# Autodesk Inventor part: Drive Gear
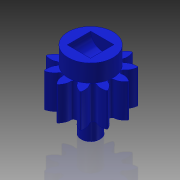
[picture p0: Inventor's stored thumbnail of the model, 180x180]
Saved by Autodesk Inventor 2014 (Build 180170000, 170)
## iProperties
Created: 2015-06
Part Number: Drive Gear
Material: Generic
Document SubType Name: Modeling
Designer: Brad Factor
Density: 1 g/cm^3
Appearance: Blue - Wall Paint - Glossy
Sending System: SolidWorks 2013
Last Author: Akzl
Author: Brad Factor
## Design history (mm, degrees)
node "Drive_Wheel"
sketch "Sketch1"
  geometry: C1 r 1.195 at (0, 0) reference; C2 r 1.194 at (0, 0); C3 r 2.4 at (0, 0) reference; C4 r 1.195 at (0, 0)
  constraints: 2 centre point, 1 coincident, 1 concentric
  dimensions: "d34" = 2.3876 diameter of C2
extrude "Shaft ID Adjustment" join sketch "Sketch1" stored distance "d1" = 10; taper "d2" = 0 deg
sketch "Sketch2"
  geometry: C1 r 2.4 at (0, 0) reference; C2 r 2.781 at (0, 0)
  constraints: 1 centre point
  dimensions: "d3" = 0.381 radial gap between concentric circles of C1 C2
extrude "Shaft OD Adjustment" join sketch "Sketch2" stored distance "d4" = 10; taper "d5" = 0 deg
sketch "Sketch3"
  geometry: C1 r 4.85 at (0, 0) reference; C2 r 5.612 at (0, 0)
  constraints: 1 centre point
  dimensions: "d6" = 0.762 radial gap between concentric circles of C1 C2
extrude "Magnet Holder OD Adjustment" join sketch "Sketch3" stored distance "d7" = 10; taper "d8" = 0 deg
sketch "Sketch4"
  geometry: C1 r 5.612 at (0, 0) reference; C2 r 2.781 at (0, 0) reference; C3 r 5.612 at (0, 0); C4 r 2.781 at (0, 0)
  constraints: 2 centre point, 2 coincident, 2 concentric
extrude "Magnet Holder Depth Adjustment" join sketch "Sketch4" distance "d17" = 0.79375; taper "d18" = 0 deg
chamfer "Outer Shaft Chamfer" distance "d9" = 0.254; stored, may be unused: second distance "d10" = 1.25, angle "d11" = 45 deg
chamfer "Inner Shaft Chamfer" distance "d12" = 0.254; stored, may be unused: second distance "d13" = 1.25, angle "d14" = 45 deg
feature "Magnet Recess Adjustment" dims "d15" = 0.127, "d16" = 0.127
workplane "Work Plane1"
workplane "Work Plane2"
sketch "Sketch5"
  geometry: C1 r 2.781 at (0, 0) reference; C2 r 5.612 at (0, 0) reference; C3 r 2.781 at (0, 0); C4 r 5.612 at (0, 0)
  constraints: 2 centre point, 2 coincident, 2 concentric
extrude "Gear Root Depth" join sketch "Sketch5" stored distance "d20" = 10; taper "d21" = 0 deg
sketch "Sketch6"
  geometry: C1 r 5.612 at (0, 0) reference; C2 r 9.792 at (0, 0); C3 r 5.612 at (0, 0)
  constraints: 2 centre point, 2 coincident, 1 concentric
  dimensions: "d22" = 19.5834 diameter of C2
extrude "Gear OD Extrusion" join sketch "Sketch6" stored distance "d23" = 10; taper "d24" = 0 deg
sketch "Sketch8"
  geometry: C1 r 7.761 at (0, 0) reference; C2 r 7.293 at (0, 0) reference; C3 r 6.622 at (0, 0) reference; A1 r 9.796 centre (0, 0) between (-2.559, 9.456) and (2.559, 9.456) reference; 54 further points
  constraints: 4 centre point, 2 point on circle, 115 other
extrude "Gear Tooth" cut sketch "Sketch8" stored distance "d25" = 10; taper "d26" = 0 deg
pattern_circular "Gear Tooth Circular Pattern" dims angle "d28" = 360 deg
sketch "Sketch10" dims "d35" = 0.127
  geometry: A1 r 9.792 centre (4.438, -6.701) between (1.754, 2.715) and (1.348, 2.59) reference; A2 r 9.792 centre (4.438, -6.701) between (-2.911, -0.23) and (-3.185, -0.555) reference; A3 r 9.792 centre (4.438, -6.701) between (-5.243, -5.231) and (-5.297, -5.652) reference; A4 r 9.792 centre (4.438, -6.701) between (-4.501, -10.698) and (-4.319, -11.082) reference; A5 r 9.792 centre (4.438, -6.701) between (-0.921, -14.896) and (-0.561, -15.121) reference; A6 r 9.792 centre (4.438, -6.701) between (4.36, -16.493) and (4.785, -16.487) reference; A7 r 9.792 centre (4.438, -6.701) between (9.666, -14.98) and (10.02, -14.746) reference; A8 r 9.792 centre (4.438, -6.701) between (13.312, -10.839) and (13.483, -10.451) reference; A9 r 9.792 centre (4.438, -6.701) between (14.141, -5.385) and (14.075, -4.965) reference; A10 r 9.792 centre (4.438, -6.701) between (11.889, -0.348) and (11.606, -0.031) reference; A11 r 9.792 centre (4.438, -6.701) between (7.271, 2.672) and (6.862, 2.786) reference; A12 r 9.665 centre (4.438, -6.701) between (1.734, 2.577) and (1.443, 2.488); A13 r 9.665 centre (4.438, -6.701) between (-2.853, -0.358) and (-3.05, -0.59); A14 r 9.665 centre (4.438, -6.701) between (-5.126, -5.307) and (-5.165, -5.609); A15 r 9.665 centre (4.438, -6.701) between (-4.361, -10.698) and (-4.231, -10.974); A16 r 9.665 centre (4.438, -6.701) between (-0.803, -14.821) and (-0.545, -14.982); A17 r 9.665 centre (4.438, -6.701) between (4.419, -16.366) and (4.723, -16.362); A18 r 9.665 centre (4.438, -6.701) between (9.647, -14.842) and (9.901, -14.674); A19 r 9.665 centre (4.438, -6.701) between (13.221, -10.734) and (13.344, -10.455); A20 r 9.665 centre (4.438, -6.701) between (14.007, -5.345) and (13.96, -5.044); A21 r 9.665 centre (4.438, -6.701) between (11.755, -0.387) and (11.552, -0.159); A22 r 9.665 centre (4.438, -6.701) between (7.179, 2.567) and (6.886, 2.648)
  constraints: 22 point on circle, 21 concentric, 11 centre point, 44 other
extrude "Gear Tolerance Cut" cut sketch "Sketch10" stored distance "d36" = 25.4; taper "d37" = 0 deg
sketch "Sketch11"
  geometry: C1 r 6.495 at (4.376, -6.584); C2 r 9.665 at (4.376, -6.584); A1 r 9.665 centre (4.376, -6.584) between (7.102, 2.689) and (6.808, 2.77) reference; 1 further point
  constraints: 2 centre point, 2 coincident, 1 concentric, 2 other
extrude "Gear Tooth Relief" cut sketch "Sketch11" stored distance "d38" = 12.7; taper "d39" = 0 deg
node "Cut-Extrude3"
node "Base1"
other parameters: "d19" = -17.4625, "d30" = -14.7701
